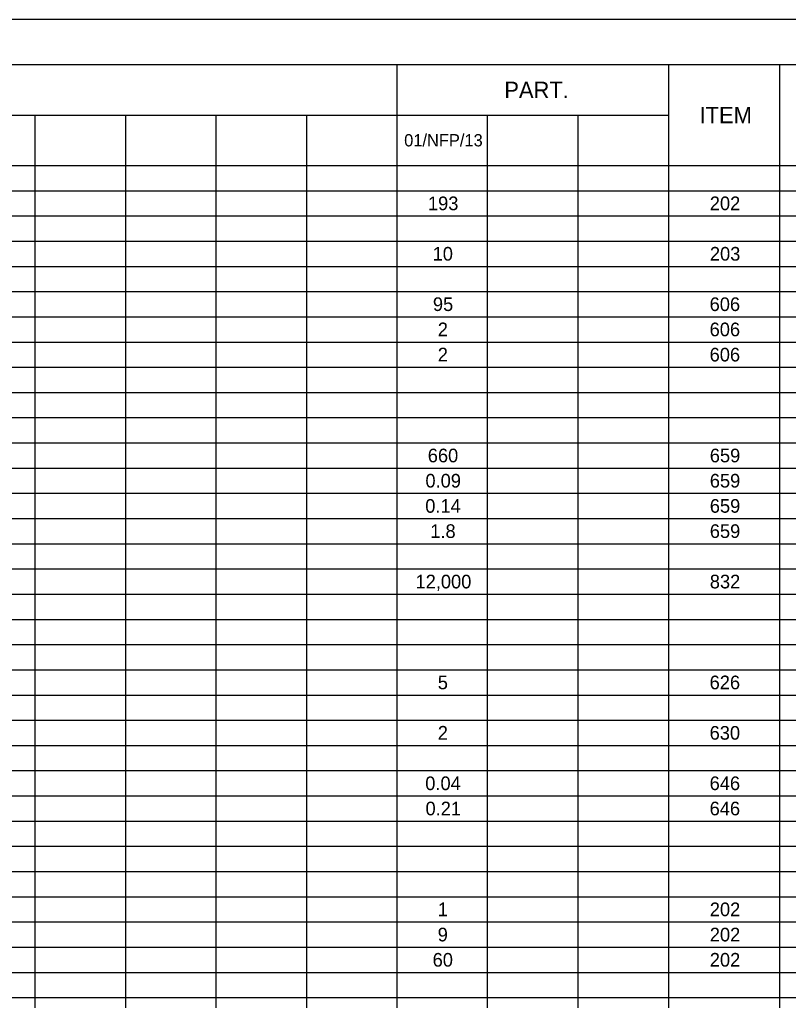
# Model space of a CAD drawing. Extents: x 0 to 34, y 0 to 22.
# Drawn here: x 8.36 to 16.9, y 11.11 to 22 of the extents above; entities that cross this region are included whole.
import ezdxf

# ---------------------------------------------------------------- set-up
doc = ezdxf.new("R2010")
doc.units = 0
for name, color, linetype in [('Default', 7, 'Continuous'), ('SH_Border', 7, 'Continuous'), ('SH_Cut_Line', 7, 'Continuous')]:
    doc.layers.add(name, color=color, linetype=linetype)

msp = doc.modelspace()

# ---------------------------------------------------------------- linework, layer by layer
at = {"layer": 'Default'}
for p, q in [((1.5, 21.5), (32.004, 21.5)), ((12.552, 21.5), (12.552, 0.5)), ((15.566, 21.5), (15.566, 0.5)), ((16.801, 21.5), (16.801, 0.5)), ((1.5, 20.94), (15.566, 20.94)), ((8.533, 20.94), (8.533, 0.5)), ((9.538, 20.94), (9.538, 0.5)), ((10.542, 20.94), (10.542, 0.5)), ((11.547, 20.94), (11.547, 0.5)), ((13.556, 20.94), (13.556, 0.5)), ((14.561, 20.94), (14.561, 0.5)), ((1.5, 20.38), (32.004, 20.38)), ((1.5, 20.1), (32.004, 20.1)), ((1.5, 19.82), (32.004, 19.82)), ((1.5, 19.54), (32.004, 19.54)), ((1.5, 19.26), (32.004, 19.26)), ((1.5, 18.98), (32.004, 18.98)), ((1.5, 18.7), (32.004, 18.7)), ((1.5, 18.42), (32.004, 18.42)), ((1.5, 18.14), (32.004, 18.14)), ((1.5, 17.86), (32.004, 17.86)), ((1.5, 17.58), (32.004, 17.58)), ((1.5, 17.3), (32.004, 17.3)), ((1.5, 17.02), (32.004, 17.02)), ((1.5, 16.74), (32.004, 16.74)), ((1.5, 16.46), (32.004, 16.46)), ((1.5, 16.18), (32.004, 16.18)), ((1.5, 15.9), (32.004, 15.9)), ((1.5, 15.62), (32.004, 15.62)), ((1.5, 15.34), (32.004, 15.34)), ((1.5, 15.06), (32.004, 15.06)), ((1.5, 14.78), (32.004, 14.78)), ((1.5, 14.5), (32.004, 14.5)), ((1.5, 14.22), (32.004, 14.22)), ((1.5, 13.94), (32.004, 13.94)), ((1.5, 13.66), (32.004, 13.66)), ((1.5, 13.38), (32.004, 13.38)), ((1.5, 13.1), (32.004, 13.1)), ((1.5, 12.82), (32.004, 12.82)), ((1.5, 12.54), (32.004, 12.54)), ((1.5, 12.26), (32.004, 12.26)), ((1.5, 11.98), (32.004, 11.98)), ((1.5, 11.7), (32.004, 11.7)), ((1.5, 11.42), (32.004, 11.42)), ((1.5, 11.14), (32.004, 11.14))]:
    msp.add_line(p, q, dxfattribs=at)
at = {"layer": 'SH_Border'}
msp.add_lwpolyline([(1.5, 21.5), (33.5, 21.5), (33.5, 0.5), (1.5, 0.5)], close=True, dxfattribs=at)
at = {"layer": 'SH_Cut_Line'}
msp.add_lwpolyline([(0, 0), (34, 0), (34, 22), (0, 22)], close=True, dxfattribs=at)

# ---------------------------------------------------------------- texts
at = {"layer": 'Default'}
for s, height, p in [('PART.', 0.1818, (13.745, 21.129)), ('ITEM', 0.1818, (15.912, 20.849)), ('01/NFP/13', 0.1364, (12.633, 20.592)), ('193', 0.1515, (12.897, 19.884)), ('202', 0.1515, (16.026, 19.884)), ('10', 0.1515, (12.949, 19.324)), ('203', 0.1515, (16.027, 19.324)), ('95', 0.1515, (12.952, 18.764)), ('606', 0.1515, (16.024, 18.764)), ('2', 0.152, (13.006, 18.484)), ('606', 0.1515, (16.024, 18.484)), ('2', 0.152, (13.006, 18.204)), ('606', 0.1515, (16.024, 18.204)), ('660', 0.1515, (12.895, 17.084)), ('659', 0.1515, (16.026, 17.084)), ('0.09', 0.1515, (12.869, 16.804)), ('659', 0.1515, (16.026, 16.804)), ('0.14', 0.1515, (12.867, 16.524)), ('659', 0.1515, (16.026, 16.524)), ('1.8', 0.1515, (12.923, 16.244)), ('659', 0.1515, (16.026, 16.244)), ('12,000', 0.1515, (12.759, 15.684)), ('832', 0.1515, (16.026, 15.684)), ('5', 0.152, (13.006, 14.564)), ('626', 0.1515, (16.024, 14.564)), ('2', 0.152, (13.006, 14.004)), ('630', 0.1515, (16.024, 14.004)), ('0.04', 0.1515, (12.867, 13.444)), ('646', 0.1515, (16.024, 13.444)), ('0.21', 0.1515, (12.87, 13.164)), ('646', 0.1515, (16.024, 13.164)), ('202', 0.1515, (16.026, 12.044)), ('1', 0.152, (13.006, 12.044)), ('9', 0.152, (13.005, 11.764)), ('202', 0.1515, (16.026, 11.764)), ('60', 0.1515, (12.949, 11.484)), ('202', 0.1515, (16.026, 11.484))]:
    msp.add_text(s, height=height, dxfattribs=at).set_placement(p)

doc.saveas('drawing.dxf')
